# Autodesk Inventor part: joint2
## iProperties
Author: chr
Created: 2002-03
Part Number: joint2
Material: Par défaut
Document SubType Name: Modélisation
Designer: chr
Control State: 0
Master: False
Checked Out: False
PropertySet Name: Design Tracking Control
Shininess: 20.0
Angle Display Precision: 2
Document Length Units: 11269
Document Angle Units: 11283
Document Time Units: 11279
Document Mass Units: 11290
Document Length Units Precision: 3
Document Angle Units Precision: 2
Compacted: False
PropertySet Name: _Private Model Information
Density: 0.0
Volumn: 0.0
Area: 0.0
PropertySet Name: Model Information
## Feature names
1. Balayage1
